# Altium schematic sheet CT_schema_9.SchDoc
size 277 x 170 mm
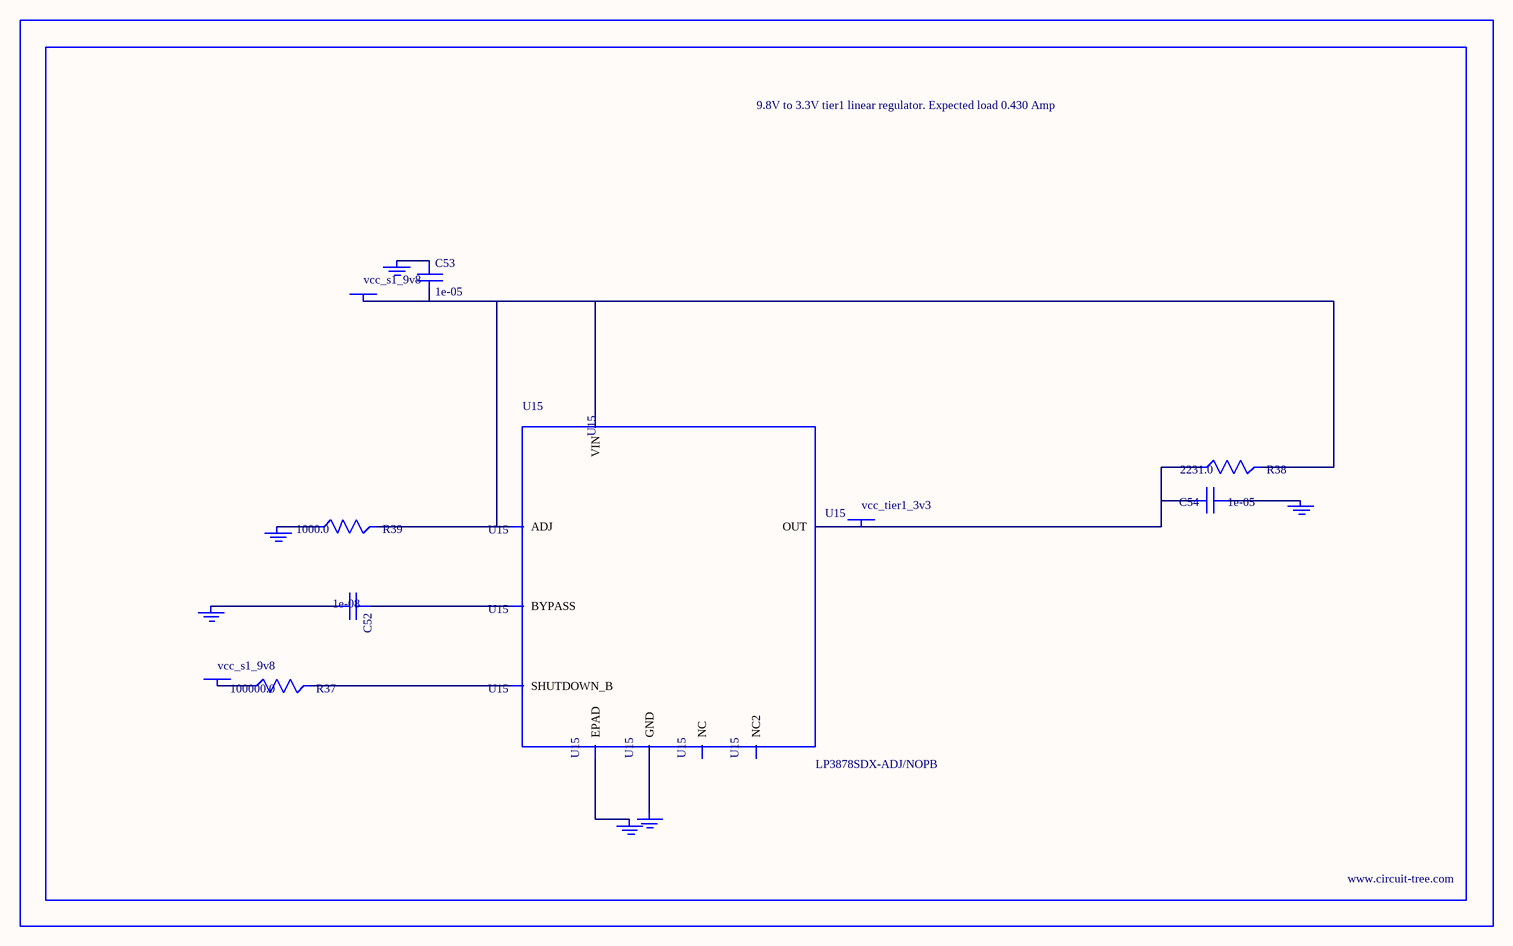
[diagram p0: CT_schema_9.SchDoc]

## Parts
BORDER8  (no value)
C52  1e-08  [C0402]
C53  1e-05  [C1206]
C54  1e-05  [C1210]
GND_INSTANCE_8_0  (no value)
GND_INSTANCE_8_1  (no value)
GND_INSTANCE_8_2  (no value)
GND_INSTANCE_8_3  (no value)
GND_INSTANCE_8_4  (no value)
GND_INSTANCE_8_5  (no value)
POWER_INSTANCE_8_0  vcc_s1_9v8
POWER_INSTANCE_8_1  vcc_s1_9v8
POWER_INSTANCE_8_2  vcc_tier1_3v3
R37  100000.0  [R0603]
R38  2231.0  [R0603]
R39  1000.0  [R0603]
U15  LP3878SDX-ADJ/NOPB  [WSON-8]

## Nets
NetC52_1: C52.1 U15.1(BYPASS)
NetC52_2: C52.2 GND_INSTANCE_8_0.0(GND)
NetC53_1: C53.1 GND_INSTANCE_8_1.0(GND)
NetC53_2: C53.2 POWER_INSTANCE_8_0.0(PWR) R38.2 R39.2 U15.4(VIN) U15.6(ADJ)
NetC54_1: C54.1 GND_INSTANCE_8_2.0(GND)
NetC54_2: C54.2 POWER_INSTANCE_8_2.0(PWR) R38.1 U15.5(OUT)
NetGND_INSTANCE_8_3_0: GND_INSTANCE_8_3.0(GND) R39.1
NetGND_INSTANCE_8_4_0: GND_INSTANCE_8_4.0(GND) U15.PAD(EPAD)
NetGND_INSTANCE_8_5_0: GND_INSTANCE_8_5.0(GND) U15.3(GND)
NetPOWER_INSTANCE_8_1_0: POWER_INSTANCE_8_1.0(PWR) R37.1
NetR37_2: R37.2 U15.8(SHUTDOWN_B)

Not connected (* = marked no-connect by the designer): U15 2(NC) 7(NC2)

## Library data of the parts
BORDER8 = BORDER_PAGE8
C52 = C0402C103K3RAC
C53 = C1206C106K3RACTU
C54 = GRM32DR61E106MA12L
GND_INSTANCE_8_0-GND_INSTANCE_8_5 = GND
POWER_INSTANCE_8_0-POWER_INSTANCE_8_2 = PWR
R37 = RC0603JR-07100KL
R38 = R38
R39 = RC0603JR-071KL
